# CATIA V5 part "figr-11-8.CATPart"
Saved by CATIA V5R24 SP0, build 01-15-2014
Part number: Part1
Bounding box of the stored display mesh (mm): x -50 to 50, y -39.834 to 41.856, z -25 to 25
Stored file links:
  D:\KAVITA\CATIA V5-6R2014 Project_ Kavita\CATIA V5-6R2014_partfiles\Partfiles\c11_catia_v5-6r2014_prt\figr-11-8.CATPart
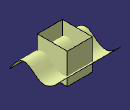
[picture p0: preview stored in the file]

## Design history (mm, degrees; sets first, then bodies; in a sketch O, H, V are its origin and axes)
Set1
  Sketch1 on yz-plane, origin (0, 0, 0), H (0, 1, 0), V (0, 0, 1)
    spline S1 through (-39.8338, -18.0686) (-4.7892, 0) (1.9431, -5.3632) (41.8556, 3.6938)
    point P1 (-4.7892, 0)
    coincidence: P1 H
  Extrude1: Element1 Sketch1, Lim1 50, Lim2 50, Direction yz-plane
  Sketch2 on xy-plane, origin (0, 0, 0), H (1, 0, 0), V (0, 1, 0)
    line L1 (-20.1634, 25.5896) -> (20.7534, 25.5896)
    line L2 (20.7534, 25.5896) -> (20.7534, -23.3463)
    line L3 (20.7534, -23.3463) -> (-20.1634, -23.3463)
    line L4 (-20.1634, -23.3463) -> (-20.1634, 25.5896)
    horizontal: L1 H, L3 H
    vertical: L2 V, L4 V
  Extrude2: Element1 Sketch2, Lim1 25, Lim2 25, Direction xy-plane
Body1 (main body)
